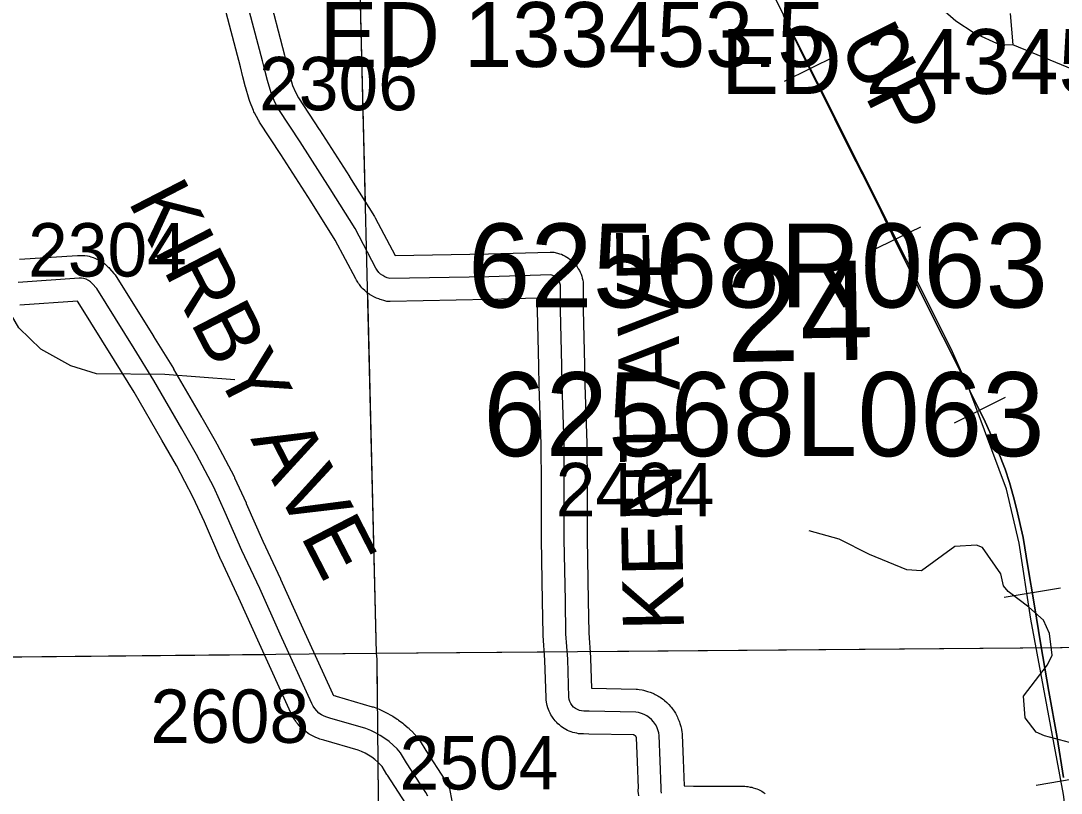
# Model space of a CAD drawing. Extents: x 23.6 to 68.7, y -63 to -29.
# Drawn here: x 43.335 to 44.699, y -55.816 to -54.804 of the extents above; entities that cross this region are included whole.
import ezdxf

# ---------------------------------------------------------------- set-up
doc = ezdxf.new("R2010")
doc.units = 0
for name, color, linetype in [('tdCoHydroRiver', 7, 'Continuous'), ('tdCoRRCL', 7, 'Continuous'), ('tdCoRROwnerTxt', 7, 'Continuous'), ('tdCoSecRdNmbr', 7, 'Continuous'), ('tdCoSecRdTxt', 7, 'Continuous'), ('tdCoSecRteBand', 7, 'Continuous'), ('tdCoSecRteCL', 7, 'Continuous'), ('tdCoSectLine', 7, 'Continuous'), ('tdCoSectLinePart', 7, 'Continuous'), ('tdCoSectNmbr', 7, 'Continuous'), ('tdCoStrucPriMaintName', 7, 'Continuous'), ('tdCoStrucSecCoName', 7, 'Continuous'), ('tdCoSurfEarth', 7, 'Continuous'), ('tdCoSurfGravel', 7, 'Continuous')]:
    doc.layers.add(name, color=color, linetype=linetype)

msp = doc.modelspace()

# ---------------------------------------------------------------- linework, layer by layer
at = {"layer": 'tdCoHydroRiver'}
for points in [[(43.6152, -55.2742), (43.5236, -55.2672), (43.4336, -55.2665), (43.4003, -55.2557), (43.3607, -55.234), (43.332, -55.2059), (43.3143, -55.176), (43.3078, -55.1556), (43.3025, -55.0972), (43.2945, -55.0799), (43.2944, -55.0752), (43.2881, -55.0689), (43.28, -55.0501), (43.2465, -55.0141), (43.221, -54.9875), (43.1574, -54.9376), (43.1253, -54.8858), (43.1183, -54.8101), (43.1101, -54.7849)], [(44.6355, -54.8351), (44.6197, -54.8353), (44.5848, -54.8198), (44.561, -54.8042), (44.5435, -54.7886)], [(44.632, -54.7941), (44.6355, -54.8351)], [(44.9055, -55.6692), (44.8999, -55.4167), (44.8865, -55.3379), (44.8832, -55.319), (44.8813, -55.2874), (44.8808, -55.229), (44.9071, -55.1767), (44.9211, -55.156), (44.9459, -55.1084), (44.9489, -55.0926), (44.9469, -55.0468), (44.9341, -55.0312), (44.8944, -55.0063), (44.8626, -54.9766), (44.8418, -54.95), (44.8385, -54.9389), (44.8067, -54.9124), (44.7559, -54.8845), (44.6355, -54.8351)], [(44.7232, -55.753), (44.6773, -55.7408), (44.6662, -55.7362), (44.6518, -55.7174), (44.6499, -55.689), (44.6811, -55.6476), (44.6873, -55.635), (44.6839, -55.6066), (44.6758, -55.5893), (44.6567, -55.5721), (44.6297, -55.5518), (44.6233, -55.544), (44.62, -55.5283), (44.596, -55.4938), (44.5881, -55.4907), (44.5597, -55.4925), (44.5158, -55.5245), (44.4968, -55.5231), (44.4477, -55.5031), (44.408, -55.4829), (44.3685, -55.4722)]]:
    msp.add_lwpolyline(points, dxfattribs=at)
at = {"layer": 'tdCoRRCL'}
for p, q in [((44.4031, -54.8501), (44.3358, -54.8832)), ((44.5145, -55.0742), (44.447, -55.1069)), ((44.6258, -55.2975), (44.5587, -55.3311)), ((44.6983, -55.5471), (44.6243, -55.5593)), ((44.74, -55.7933), (44.6661, -55.8061))]:
    msp.add_line(p, q, dxfattribs=at)
for points in [[(44.743, -58.0271), (44.7693, -57.8915), (44.8118, -57.6985), (44.8145, -57.6495), (44.7973, -57.4824), (44.7734, -57.2758), (44.7492, -57.036), (44.7285, -56.8389), (44.7193, -56.6843), (44.7262, -56.58), (44.7557, -56.5166), (44.7586, -56.2741), (44.742, -56.1303), (44.7022, -55.8178), (44.6591, -55.5877), (44.644, -55.4884), (44.6276, -55.4175), (44.5791, -55.2885), (44.555, -55.2334), (44.3204, -54.7666)], [(44.3348, -54.7965), (44.3565, -54.8403), (44.3709, -54.8696), (44.3893, -54.9061), (44.4024, -54.9323), (44.4218, -54.9721), (44.4386, -55.0044), (44.458, -55.0434), (44.4823, -55.0938), (44.4981, -55.1247), (44.5183, -55.1664), (44.5442, -55.2183), (44.5696, -55.2683), (44.5843, -55.2985), (44.5977, -55.3252), (44.6071, -55.3465), (44.6101, -55.3535), (44.6163, -55.3682), (44.6255, -55.3913), (44.6315, -55.4086), (44.6365, -55.4275), (44.6407, -55.4427), (44.6491, -55.4807), (44.6556, -55.5189), (44.6638, -55.568), (44.6724, -55.6217), (44.6831, -55.6825), (44.6939, -55.7431), (44.7023, -55.7955)], [(44.7023, -55.7955), (44.6939, -55.7431), (44.6831, -55.6825), (44.6724, -55.6217), (44.6638, -55.568), (44.6556, -55.5189), (44.6491, -55.4807), (44.6407, -55.4427), (44.6365, -55.4275), (44.6315, -55.4086), (44.6255, -55.3913), (44.6163, -55.3682), (44.6101, -55.3535), (44.6071, -55.3465), (44.5977, -55.3252), (44.5843, -55.2985), (44.5696, -55.2683), (44.5442, -55.2183), (44.5183, -55.1664), (44.4981, -55.1247), (44.4823, -55.0938), (44.458, -55.0434), (44.4386, -55.0044), (44.4218, -54.9721), (44.4024, -54.9323), (44.3893, -54.9061), (44.3709, -54.8696), (44.3565, -54.8403), (44.3348, -54.7965)]]:
    msp.add_lwpolyline(points, dxfattribs=at)
at = {"layer": 'tdCoSecRteBand'}
for points in [[(43.6579, -54.7624), (43.6806, -54.8486), (43.6806, -54.8487), (43.6806, -54.8488), (43.6841, -54.8625), (43.6841, -54.8626), (43.6841, -54.8627), (43.6869, -54.874), (43.6911, -54.8883), (43.6947, -54.8973), (43.6986, -54.9045), (43.7259, -54.9459), (43.726, -54.9461), (43.7262, -54.9463), (43.7655, -55.0077), (43.7655, -55.0078), (43.7656, -55.0079), (43.7983, -55.0601), (43.7989, -55.061), (43.7994, -55.062), (43.8255, -55.1112), (43.9478, -55.109), (44.0288, -55.1067), (44.0337, -55.1066), (44.0384, -55.108), (44.041, -55.1088), (44.0436, -55.1095), (44.0459, -55.1107), (44.0484, -55.112), (44.0508, -55.1132), (44.0529, -55.1148), (44.0552, -55.1165), (44.0573, -55.1181), (44.0591, -55.12), (44.061, -55.1221), (44.0628, -55.124), (44.0642, -55.1262), (44.0657, -55.1286), (44.0672, -55.1308), (44.0682, -55.1332), (44.0693, -55.1358), (44.0703, -55.1383), (44.0709, -55.1409), (44.0715, -55.1436), (44.0721, -55.1462), (44.0722, -55.1488), (44.0723, -55.1516), (44.0723, -55.1523), (44.0723, -55.153), (44.0723, -55.1824), (44.074, -55.2547), (44.074, -55.2548), (44.074, -55.2548), (44.0745, -55.2808), (44.0769, -55.3572), (44.0769, -55.3576), (44.0769, -55.3579), (44.0773, -55.4115), (44.0773, -55.4116), (44.0773, -55.4117), (44.0774, -55.4826), (44.0789, -55.5634), (44.0789, -55.5635), (44.0789, -55.5635), (44.0796, -55.6059), (44.0818, -55.6382), (44.0818, -55.6387), (44.0819, -55.6393), (44.0832, -55.6785), (44.1416, -55.6798), (44.1436, -55.6798), (44.1456, -55.6801), (44.1494, -55.6807), (44.1511, -55.681), (44.1528, -55.6815), (44.1566, -55.6825), (44.1583, -55.683), (44.1599, -55.6836), (44.1635, -55.6851), (44.1651, -55.6857), (44.1666, -55.6865), (44.1701, -55.6884), (44.1716, -55.6892), (44.173, -55.6902), (44.1762, -55.6925), (44.1776, -55.6934), (44.1789, -55.6946), (44.1818, -55.6972), (44.1831, -55.6983), (44.1843, -55.6996), (44.1869, -55.7025), (44.1881, -55.7038), (44.189, -55.7052), (44.1913, -55.7084), (44.1923, -55.7098), (44.1931, -55.7113), (44.195, -55.7148), (44.1959, -55.7163), (44.1965, -55.7179), (44.198, -55.7215), (44.1986, -55.7231), (44.1991, -55.7248), (44.2002, -55.7286), (44.2006, -55.7302), (44.2009, -55.7319), (44.2015, -55.7358), (44.2018, -55.7376), (44.2019, -55.7393), (44.2032, -55.7722), (44.2032, -55.7723), (44.2032, -55.7723), (44.2044, -55.8065), (44.2169, -55.8067), (44.2803, -55.8069), (44.2807, -55.8069), (44.2812, -55.8069), (44.2841, -55.807), (44.2862, -55.8071), (44.2883, -55.8074), (44.2912, -55.8079), (44.2932, -55.8083), (44.2952, -55.8089), (44.2981, -55.8098), (44.3, -55.8104), (44.3019, -55.8113), (44.3046, -55.8126), (44.3065, -55.8135), (44.3082, -55.8147), (44.3107, -55.8163)], [(44.145, -55.8193), (44.1446, -55.8159), (44.1444, -55.8138), (44.1444, -55.8118), (44.1445, -55.8094), (44.1432, -55.7746), (44.142, -55.7435), (44.1419, -55.7431), (44.1418, -55.7426), (44.1416, -55.7421), (44.1414, -55.7417), (44.1411, -55.7413), (44.1408, -55.7409), (44.1404, -55.7406), (44.14, -55.7403), (44.1395, -55.7401), (44.1391, -55.7399), (44.1386, -55.7398), (44.1384, -55.7397), (44.0795, -55.7385), (44.0795, -55.7385), (44.0795, -55.7385), (44.0724, -55.7383), (44.072, -55.7383), (44.0715, -55.7383), (44.0686, -55.7381), (44.0662, -55.738), (44.064, -55.7375), (44.0611, -55.7369), (44.0588, -55.7364), (44.0566, -55.7356), (44.0538, -55.7346), (44.0516, -55.7337), (44.0496, -55.7326), (44.047, -55.7311), (44.045, -55.7299), (44.0432, -55.7285), (44.0409, -55.7266), (44.0391, -55.7252), (44.0375, -55.7235), (44.0355, -55.7213), (44.0339, -55.7196), (44.0326, -55.7176), (44.031, -55.7152), (44.0297, -55.7132), (44.0287, -55.7111), (44.0275, -55.7084), (44.0265, -55.7063), (44.0258, -55.7041), (44.025, -55.7012), (44.0244, -55.699), (44.0241, -55.6966), (44.0237, -55.6937), (44.0236, -55.6924), (44.0235, -55.6911), (44.0219, -55.6418), (44.0197, -55.6093), (44.0196, -55.6085), (44.0196, -55.6077), (44.0189, -55.5645), (44.0174, -55.4835), (44.0174, -55.4832), (44.0174, -55.483), (44.0173, -55.4119), (44.017, -55.3587), (44.0145, -55.2825), (44.0145, -55.2823), (44.0145, -55.2821), (44.014, -55.256), (44.0124, -55.1834), (44.0123, -55.1831), (44.0123, -55.1827), (44.0123, -55.1672), (43.9493, -55.169), (43.9492, -55.169), (43.949, -55.169), (43.819, -55.1713), (43.8148, -55.1714), (43.8108, -55.1703), (43.8076, -55.1695), (43.8057, -55.169), (43.804, -55.1682), (43.8009, -55.167), (43.7991, -55.1663), (43.7974, -55.1653), (43.7945, -55.1637), (43.7928, -55.1628), (43.7913, -55.1616), (43.7886, -55.1596), (43.7871, -55.1585), (43.7857, -55.1571), (43.7833, -55.1548), (43.7819, -55.1535), (43.7807, -55.152), (43.7786, -55.1494), (43.7774, -55.1479), (43.7764, -55.1462), (43.7747, -55.1434), (43.7742, -55.1426), (43.7738, -55.1419), (43.7469, -55.091), (43.7148, -55.04), (43.6757, -54.9788), (43.6477, -54.9364), (43.647, -54.9352), (43.6463, -54.9339), (43.641, -54.9241), (43.6403, -54.9227), (43.6397, -54.9212), (43.6349, -54.9093), (43.6344, -54.908), (43.6339, -54.9066), (43.6292, -54.8903), (43.629, -54.8897), (43.6288, -54.889), (43.6259, -54.8771), (43.6225, -54.8637), (43.5999, -54.7777)], [(43.3326, -55.1162), (43.4088, -55.111), (43.4099, -55.111), (43.411, -55.111), (43.4142, -55.111), (43.4164, -55.111), (43.4187, -55.1113), (43.4219, -55.1118), (43.4241, -55.1122), (43.4262, -55.1128), (43.4293, -55.1138), (43.4315, -55.1145), (43.4335, -55.1154), (43.4364, -55.1169), (43.4384, -55.1178), (43.4403, -55.1191), (43.4429, -55.1209), (43.4448, -55.1222), (43.4464, -55.1238), (43.4488, -55.126), (43.4499, -55.127), (43.4509, -55.1281), (43.4566, -55.1347), (43.4582, -55.1365), (43.4595, -55.1386), (43.5085, -55.217), (43.5086, -55.2171), (43.5086, -55.2172), (43.5346, -55.2594), (43.5348, -55.2597), (43.535, -55.2601), (43.5716, -55.3232), (43.5717, -55.3233), (43.5718, -55.3234), (43.591, -55.3571), (43.5912, -55.3575), (43.5915, -55.358), (43.6142, -55.401), (43.6146, -55.4018), (43.6149, -55.4025), (43.63, -55.4356), (43.6301, -55.4358), (43.6302, -55.4361), (43.6518, -55.4855), (43.6751, -55.5351), (43.6752, -55.5353), (43.6753, -55.5355), (43.7022, -55.5953), (43.7433, -55.6854), (43.744, -55.6868), (43.7442, -55.6871), (43.7444, -55.6873), (43.7446, -55.6875), (43.7448, -55.6877), (43.7451, -55.6879), (43.7454, -55.688), (43.7475, -55.6885), (43.7479, -55.6886), (43.7483, -55.6887), (43.7953, -55.7026), (43.7966, -55.7029), (43.7978, -55.7034), (43.8044, -55.706), (43.8053, -55.7063), (43.8062, -55.7068), (43.8126, -55.7098), (43.8135, -55.7102), (43.8144, -55.7107), (43.8206, -55.7141), (43.8215, -55.7146), (43.8223, -55.7152), (43.8283, -55.719), (43.8291, -55.7196), (43.8299, -55.7202), (43.8356, -55.7244), (43.8364, -55.725), (43.8371, -55.7256), (43.8425, -55.7302), (43.8433, -55.7309), (43.844, -55.7316), (43.849, -55.7365), (43.8498, -55.7372), (43.8504, -55.738), (43.8551, -55.7433), (43.857, -55.7454), (43.8584, -55.7478), (43.8659, -55.7602), (43.8908, -55.7985), (43.8915, -55.7996), (43.8921, -55.8007), (43.8947, -55.8057), (43.897, -55.81), (43.8978, -55.8148), (43.9002, -55.8287)], [(43.8395, -55.8297), (43.8153, -55.7924), (43.815, -55.792), (43.8148, -55.7915), (43.8085, -55.7811), (43.8063, -55.7787), (43.8027, -55.7752), (43.7989, -55.7719), (43.7948, -55.7688), (43.7906, -55.7661), (43.7862, -55.7636), (43.7816, -55.7615), (43.7772, -55.7598), (43.7318, -55.7464), (43.7284, -55.7455), (43.7266, -55.7451), (43.7249, -55.7444), (43.7213, -55.7429), (43.7196, -55.7423), (43.718, -55.7414), (43.7145, -55.7395), (43.7129, -55.7386), (43.7114, -55.7376), (43.7082, -55.7352), (43.7067, -55.7342), (43.7053, -55.7329), (43.7024, -55.7303), (43.7011, -55.729), (43.6999, -55.7276), (43.6973, -55.7246), (43.6961, -55.7232), (43.6951, -55.7217), (43.6929, -55.7184), (43.6919, -55.7169), (43.6911, -55.7152), (43.6893, -55.7117), (43.6891, -55.7112), (43.6889, -55.7107), (43.6476, -55.6201), (43.6476, -55.6201), (43.6476, -55.62), (43.6207, -55.5604), (43.5973, -55.5107), (43.5971, -55.5103), (43.5969, -55.5099), (43.5754, -55.4603), (43.5607, -55.4283), (43.5386, -55.3864), (43.5197, -55.3532), (43.4833, -55.2905), (43.4576, -55.2487), (43.4099, -55.1724), (43.4088, -55.1712), (43.3332, -55.1763)]]:
    msp.add_lwpolyline(points, dxfattribs=at)
at = {"layer": 'tdCoSecRteCL'}
for points in [[(44.1748, -55.8161), (44.1744, -55.8127), (44.1745, -55.8093), (44.1732, -55.7734), (44.1719, -55.7405), (44.1713, -55.7367), (44.1702, -55.7329), (44.1687, -55.7292), (44.1668, -55.7258), (44.1646, -55.7226), (44.1619, -55.7196), (44.159, -55.717), (44.1558, -55.7148), (44.1523, -55.7129), (44.1487, -55.7114), (44.1449, -55.7104), (44.141, -55.7098), (44.0802, -55.7085), (44.0731, -55.7083), (44.0701, -55.7082), (44.0672, -55.7076), (44.0645, -55.7065), (44.0619, -55.705), (44.0596, -55.7032), (44.0576, -55.701), (44.0559, -55.6985), (44.0547, -55.6959), (44.0539, -55.693), (44.0535, -55.6901), (44.0519, -55.6403), (44.0496, -55.6072), (44.0489, -55.564), (44.0474, -55.4829), (44.0473, -55.4117), (44.047, -55.3581), (44.0445, -55.2815), (44.044, -55.2554), (44.0423, -55.1827), (44.0423, -55.153), (44.0422, -55.1502), (44.0416, -55.1474), (44.0405, -55.1448), (44.039, -55.1425), (44.0371, -55.1404), (44.0349, -55.1388), (44.0324, -55.1375), (44.0297, -55.1367), (43.9485, -55.139), (43.8184, -55.1413), (43.8152, -55.1404), (43.8121, -55.1392), (43.8092, -55.1376), (43.8065, -55.1356), (43.8042, -55.1333), (43.8021, -55.1306), (43.8003, -55.1278), (43.7729, -55.076), (43.7402, -55.0239), (43.7009, -54.9624), (43.6728, -54.9198), (43.6675, -54.91), (43.6627, -54.8981), (43.658, -54.8819), (43.655, -54.8699), (43.6516, -54.8562), (43.6289, -54.7701)], [(43.8683, -55.8198), (43.8656, -55.8149), (43.8405, -55.7761), (43.8327, -55.7632), (43.828, -55.758), (43.823, -55.753), (43.8176, -55.7484), (43.812, -55.7442), (43.806, -55.7404), (43.7999, -55.7369), (43.7935, -55.7339), (43.7869, -55.7313), (43.7399, -55.7175), (43.736, -55.7165), (43.7323, -55.7151), (43.7289, -55.7132), (43.7256, -55.7109), (43.7227, -55.7082), (43.7201, -55.7052), (43.718, -55.7018), (43.7162, -55.6983), (43.6749, -55.6077), (43.648, -55.5479), (43.6244, -55.4979), (43.6027, -55.4481), (43.5876, -55.415), (43.5649, -55.372), (43.5457, -55.3383), (43.509, -55.2751), (43.4831, -55.2329), (43.4341, -55.1544), (43.4283, -55.1479), (43.426, -55.1457), (43.4233, -55.1438), (43.4204, -55.1424), (43.4173, -55.1415), (43.4141, -55.141), (43.4109, -55.141), (43.3311, -55.1464)]]:
    msp.add_lwpolyline(points, dxfattribs=at)
at = {"layer": 'tdCoSectLine'}
for points in [[(43.7763, -54.6391), (43.8008, -55.6326)], [(42.791, -55.6424), (43.8008, -55.6326)], [(43.8008, -55.6326), (44.8037, -55.6241)], [(43.8008, -55.6326), (43.8014, -55.6401), (43.811, -56.6339)]]:
    msp.add_lwpolyline(points, dxfattribs=at)
at = {"layer": 'tdCoSectLinePart'}
for points in [[(43.7763, -54.6391), (43.7862, -55.0416)], [(43.7891, -55.16), (43.8008, -55.6326)], [(42.791, -55.6424), (43.6538, -55.634)], [(43.7194, -55.6334), (43.8008, -55.6326)], [(43.8008, -55.6326), (44.0204, -55.6308)], [(43.8008, -55.6326), (43.8014, -55.6401), (43.8021, -55.7056)], [(44.0804, -55.6302), (44.8037, -55.6241)], [(43.8027, -55.7762), (43.811, -56.6339)]]:
    msp.add_lwpolyline(points, dxfattribs=at)
at = {"layer": 'tdCoSurfEarth'}
msp.add_lwpolyline([(43.8683, -55.8198), (43.8656, -55.8149), (43.8405, -55.7761), (43.8327, -55.7632), (43.828, -55.758), (43.823, -55.753), (43.8176, -55.7484), (43.812, -55.7442), (43.806, -55.7404), (43.7999, -55.7369), (43.7935, -55.7339), (43.7869, -55.7313), (43.7399, -55.7175), (43.736, -55.7165), (43.7323, -55.7151), (43.7289, -55.7132), (43.7256, -55.7109), (43.7227, -55.7082), (43.7201, -55.7052), (43.718, -55.7018), (43.7162, -55.6983), (43.6749, -55.6077), (43.648, -55.5479), (43.6244, -55.4979), (43.6027, -55.4481), (43.5876, -55.415), (43.5649, -55.372), (43.5457, -55.3383), (43.509, -55.2751), (43.4831, -55.2329), (43.4341, -55.1544), (43.4283, -55.1479), (43.426, -55.1457), (43.4233, -55.1438), (43.4204, -55.1424), (43.4173, -55.1415), (43.4141, -55.141), (43.4109, -55.141), (43.3311, -55.1464)], dxfattribs=at)
at = {"layer": 'tdCoSurfGravel'}
msp.add_lwpolyline([(44.1748, -55.8161), (44.1744, -55.8127), (44.1745, -55.8093), (44.1732, -55.7734), (44.1719, -55.7405), (44.1713, -55.7367), (44.1702, -55.7329), (44.1687, -55.7292), (44.1668, -55.7258), (44.1646, -55.7226), (44.1619, -55.7196), (44.159, -55.717), (44.1558, -55.7148), (44.1523, -55.7129), (44.1487, -55.7114), (44.1449, -55.7104), (44.141, -55.7098), (44.0802, -55.7085), (44.0731, -55.7083), (44.0701, -55.7082), (44.0672, -55.7076), (44.0645, -55.7065), (44.0619, -55.705), (44.0596, -55.7032), (44.0576, -55.701), (44.0559, -55.6985), (44.0547, -55.6959), (44.0539, -55.693), (44.0535, -55.6901), (44.0519, -55.6403), (44.0496, -55.6072), (44.0489, -55.564), (44.0474, -55.4829), (44.0473, -55.4117), (44.047, -55.3581), (44.0445, -55.2815), (44.044, -55.2554), (44.0423, -55.1827), (44.0423, -55.153), (44.0422, -55.1502), (44.0416, -55.1474), (44.0405, -55.1448), (44.039, -55.1425), (44.0371, -55.1404), (44.0349, -55.1388), (44.0324, -55.1375), (44.0297, -55.1367), (43.9485, -55.139), (43.8184, -55.1413), (43.8152, -55.1404), (43.8121, -55.1392), (43.8092, -55.1376), (43.8065, -55.1356), (43.8042, -55.1333), (43.8021, -55.1306), (43.8003, -55.1278), (43.7729, -55.076), (43.7402, -55.0239), (43.7009, -54.9624), (43.6728, -54.9198), (43.6675, -54.91), (43.6627, -54.8981), (43.658, -54.8819), (43.655, -54.8699), (43.6516, -54.8562), (43.6289, -54.7701)], dxfattribs=at)

# ---------------------------------------------------------------- texts
at = {"layer": 'tdCoRROwnerTxt'}
msp.add_text('  UP  ', height=0.08, rotation=296.6807, dxfattribs=at).set_placement((44.3796, -54.7794))
msp.add_text('  UP  ', height=0.08, rotation=296.6807, dxfattribs=at).set_placement((44.3796, -54.7794))
msp.add_text('  UP  ', height=0.08, rotation=296.6807, dxfattribs=at).set_placement((44.3796, -54.7794))
at = {"layer": 'tdCoSecRdNmbr'}
for s, rotation, p in [('2306', 0.034, (43.6471, -54.9209)), ('2304', 0.0338, (43.3441, -55.1388)), ('2404', 0.0343, (44.0362, -55.4531)), ('2608', 0.0339, (43.5045, -55.7501)), ('2504', 0.0341, (43.8313, -55.8112))]:
    msp.add_text(s, height=0.07, rotation=rotation, dxfattribs=at).set_placement(p)
at = {"layer": 'tdCoSecRdTxt'}
for s, rotation, p in [('KIRBY AVE', 297.2826, (43.4744, -55.0398)), ('KENT AVE', 91, (44.2044, -55.6027))]:
    msp.add_text(s, height=0.08, rotation=rotation, dxfattribs=at).set_placement(p)
at = {"layer": 'tdCoSectNmbr'}
msp.add_text('24', height=0.13, rotation=1.0343, dxfattribs=at).set_placement((44.2604, -55.251))
at = {"layer": 'tdCoStrucPriMaintName'}
for s, p in [('62568R063', (43.921, -55.1793)), ('62568R063', (43.921, -55.1793)), ('62568R063', (43.921, -55.1793)), ('62568L063', (43.9411, -55.3742)), ('62568L063', (43.9411, -55.3742)), ('62568L063', (43.9411, -55.3742))]:
    msp.add_text(s, height=0.11, dxfattribs=at).set_placement(p)
at = {"layer": 'tdCoStrucSecCoName'}
for s, p in [('ED 133453.5', (43.7264, -54.864)), ('ED 243453.0', (44.2533, -54.8994))]:
    msp.add_text(s, height=0.085, dxfattribs=at).set_placement(p)

doc.saveas('drawing.dxf')
